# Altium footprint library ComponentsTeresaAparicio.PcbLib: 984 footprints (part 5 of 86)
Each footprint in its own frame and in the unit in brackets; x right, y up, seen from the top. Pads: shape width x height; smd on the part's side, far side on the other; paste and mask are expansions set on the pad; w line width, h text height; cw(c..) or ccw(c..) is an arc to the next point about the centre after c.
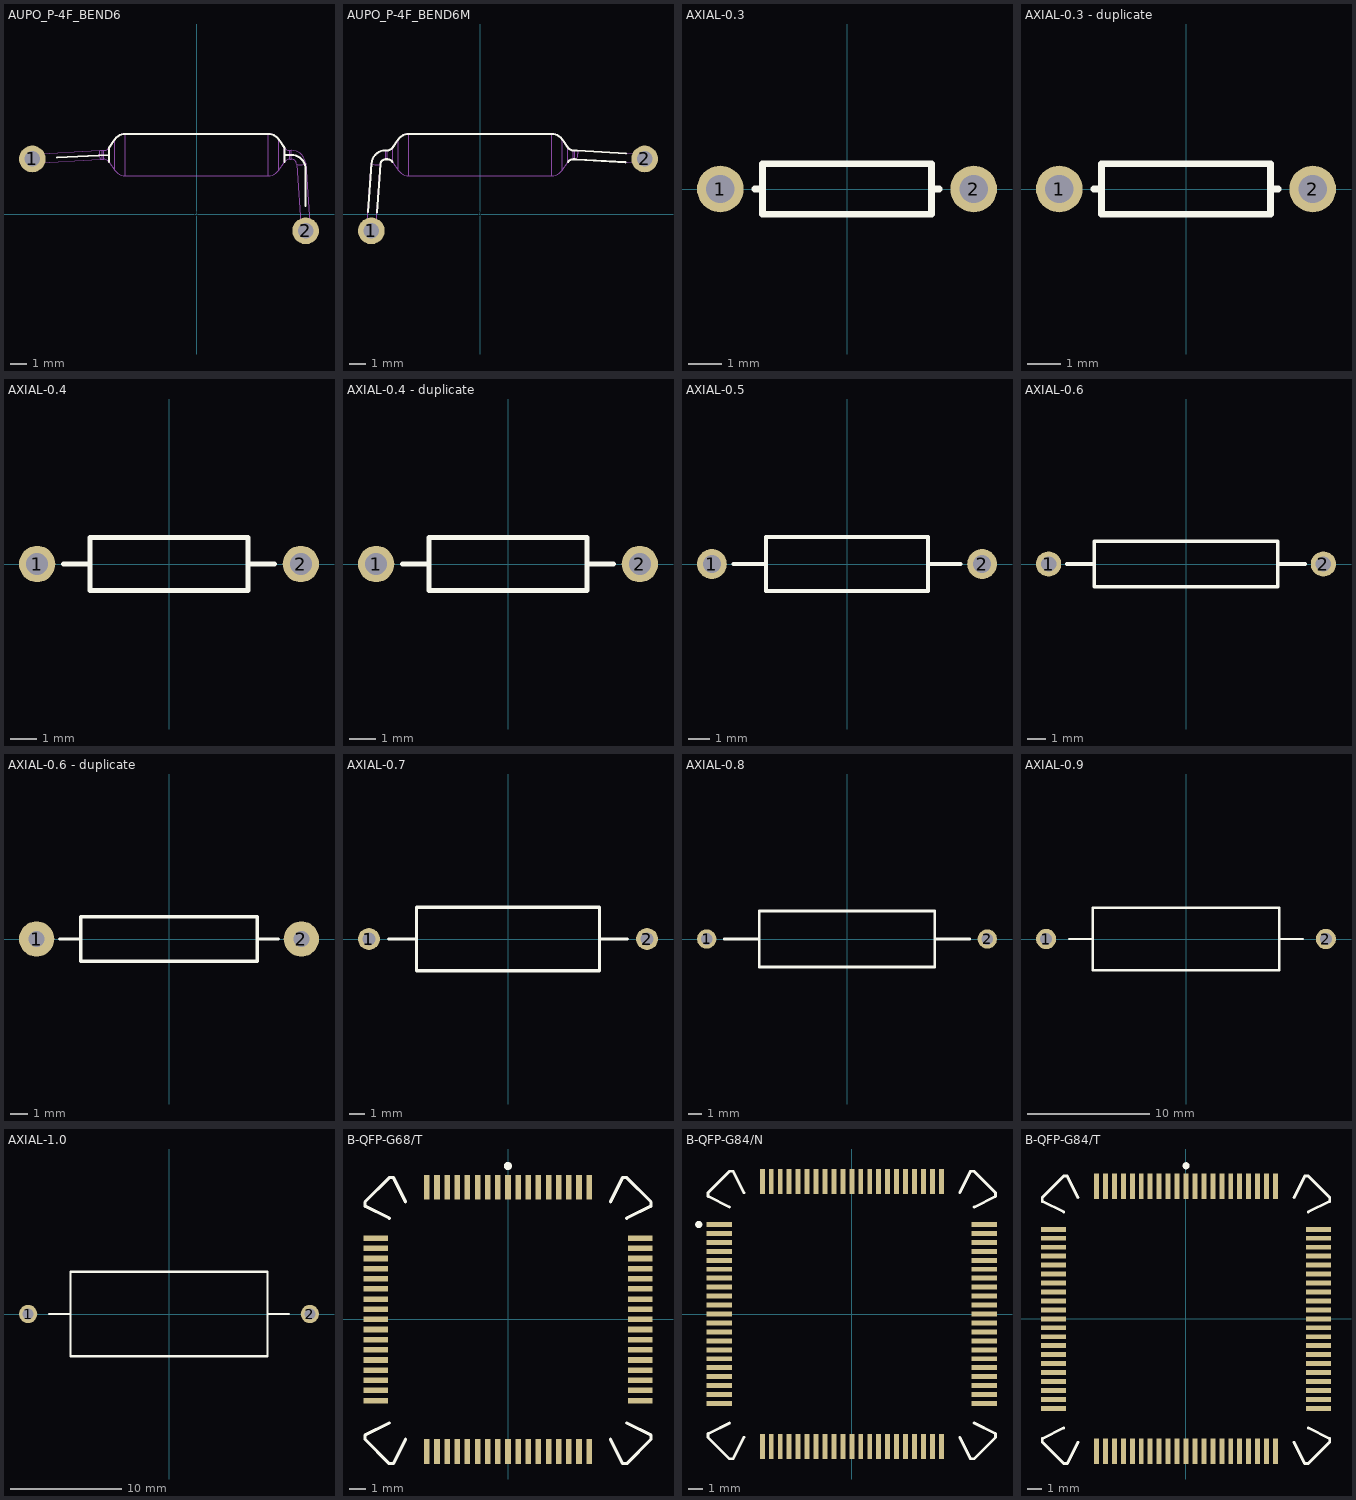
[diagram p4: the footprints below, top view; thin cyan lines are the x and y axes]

## AUPO_P-4F_BEND6 [mil] "Aupo P-4F TCO for positioning on IC legs"
height 100
pads (3):
  round 19.68 on Mech14: 0(0,0)
  round 65 / inner round 65 / far side round 90 hole 38: 1(-400,135) 2(265,-40)
Top Overlay:
  lines w5: -340.17,138.21 -213.48,145 ; -213.48,127.46 -213.48,162.54 -199.33,182.75 cw(c-173.53,164.69) -173.53,196.18 173.53,196.18 cw(c173.53,164.69) 199.33,182.75 213.48,162.54 213.48,127.46 ; 213.48,145 230,145 cw(c230,110) 265,110 265,20
Mechanical 13:
  lines w1.97: -381.43,146.96 ccw(c-359.97,137.39) -380.14,125.34 ; 252.86,-21.08 ccw(c262.11,4.31) 274.45,-19.73 274.46,-19.61 ; -235.55,155.67 ccw(c-214.1,146.11) -234.26,134.06 ; -235.55,155.67 -400.65,145.81 ccw(c-400,135) -399.35,124.19 -234.26,134.06 ; -235.55,155.67 -232.3,155.8 -230.32,155.83 ; -234.26,134.06 -232.78,134.13 -230.32,134.17 ; -230.32,134.17 -230.32,155.83 ; -230.32,134.17 -226.38,134.17 ; -230.32,155.83 -226.38,155.83 ; -226.38,134.17 cw(c-226.38,118.43) -213.48,127.46 ; -226.38,134.17 -226.38,155.83 ; -226.38,155.83 ccw(c-226.38,171.57) -213.48,162.54 ; -213.48,127.46 -199.33,107.25 ; -213.48,127.46 -213.48,162.54 ; -213.48,162.54 -199.33,182.75 ; -199.33,107.25 ccw(c-173.53,125.31) -173.53,93.82 ; -199.33,107.25 -199.33,182.75 ; -199.33,182.75 cw(c-173.53,164.69) -173.53,196.18 ; -173.53,93.82 -173.53,196.18 ; -173.53,93.82 173.53,93.82 ; -173.53,196.18 173.53,196.18 ; 173.53,93.82 ccw(c173.53,125.31) 199.33,107.25 ; 173.53,93.82 173.53,196.18 ; 173.53,196.18 cw(c173.53,164.69) 199.33,182.75 ; 199.33,107.25 199.33,182.75 ; 199.33,107.25 213.48,127.46 ; 199.33,182.75 213.48,162.54 ; 213.48,127.46 cw(c226.38,118.43) 226.38,134.17 ; 213.48,127.46 213.48,162.54 ; 213.48,162.54 ccw(c226.38,171.57) 226.38,155.83 ; 226.38,134.17 226.38,155.83 ; 226.38,134.17 230.32,134.17 ; 226.38,155.83 230.32,155.83 ; 230.32,134.17 cw(c230.47,121.52) 243.08,122.53 ; 230.32,134.17 230.32,155.83 ; 230.32,155.83 cw(c230.46,121.51) 264.69,124 ; 243.08,122.53 ccw(c252.33,147.93) 264.67,123.88 264.69,124 ; 243.08,122.53 254.2,-40.74 ccw(c265,-40) 275.83,-40 275.8,-39.26 264.69,124
3D body: height 40, standoff 0, extent -445,90.09 -355.36,179.91
3D body: height 102.87, standoff -99.49, extent -410.74,-50.8 275.83,196.09
3D body: height 40, standoff 0, extent 219.99,-84.91 309.64,4.91

## AUPO_P-4F_BEND6M [mil] "Aupo P-4F TCO for positioning on IC legs"
height 100
pads (3):
  round 19.68 on Mech14: 0(0,0)
  round 65 / inner round 65 / far side round 90 hole 38: 1(-265,-40) 2(400,135)
Top Overlay:
  lines w5: -272.66,6.54 -264.69,124.01 cw(c-230.48,121.53) -230.32,155.83 -226.38,155.83 ccw(c-226.38,171.57) -213.48,162.54 -199.33,182.75 cw(c-173.53,164.69) -173.53,196.18 173.53,196.18 cw(c173.53,164.69) 199.33,182.75 213.48,162.54 ccw(c226.38,171.57) 226.38,155.83 230.32,155.83 233.67,155.76 235.64,155.67 354.91,148.54 ; -251.05,5.07 -243.08,122.54 cw(c-230.46,121.51) -230.32,134.17 -226.38,134.17 cw(c-226.38,118.43) -213.48,127.46 ; 213.48,127.46 cw(c226.38,118.43) 226.38,134.17 230.32,134.17 231.82,134.16 234.34,134.05 353.62,126.93
Mechanical 13:
  lines w1.97: -274.43,-19.69 ccw(c-262.06,2.73) -252.83,-21.16 ; 380.23,125.34 ccw(c367.39,134.41) 382.95,136.67 383.02,139.06 382.98,141.3 382.83,143.28 382.58,144.91 382.25,146.1 381.85,146.78 381.52,146.95 ; -264.69,124.01 ccw(c-252.3,146.47) -243.08,122.54 ; -264.69,124.01 cw(c-230.48,121.53) -230.32,155.83 ; -264.69,124.01 -275.76,-39.27 ccw(c-264.96,-40) -254.16,-40.73 -243.08,122.54 ; -243.08,122.54 cw(c-230.46,121.51) -230.32,134.17 ; -230.32,134.17 -230.32,155.83 ; -230.32,134.17 -226.38,134.17 ; -230.32,155.83 -226.38,155.83 ; -226.38,134.17 cw(c-226.38,118.43) -213.48,127.46 ; -226.38,134.17 -226.38,155.83 ; -226.38,155.83 ccw(c-226.38,171.57) -213.48,162.54 ; -213.48,127.46 -213.48,162.54 ; -213.48,127.46 -199.33,107.25 ; -213.48,162.54 -199.33,182.75 ; -199.33,107.25 ccw(c-173.53,125.31) -173.53,93.82 ; -199.33,107.25 -199.33,182.75 ; -199.33,182.75 cw(c-173.53,164.69) -173.53,196.18 ; -173.53,93.82 -173.53,196.18 ; -173.53,93.82 173.53,93.82 ; -173.53,196.18 173.53,196.18 ; 173.53,93.82 ccw(c173.53,125.31) 199.33,107.25 ; 173.53,93.82 173.53,196.18 ; 173.53,196.18 cw(c173.53,164.69) 199.33,182.75 ; 199.33,107.25 199.33,182.75 ; 199.33,107.25 213.48,127.46 ; 199.33,182.75 213.48,162.54 ; 213.48,127.46 cw(c226.38,118.43) 226.38,134.17 ; 213.48,127.46 213.48,162.54 ; 213.48,162.54 ccw(c226.38,171.57) 226.38,155.83 ; 226.38,134.17 226.38,155.83 ; 226.38,134.17 230.32,134.17 ; 226.38,155.83 230.32,155.83 ; 230.32,134.17 230.32,155.83 ; 230.32,134.17 231.82,134.16 234.34,134.05 ; 230.32,155.83 233.67,155.76 235.64,155.67 ; 234.34,134.05 ccw(c221.51,143.13) 237.07,145.38 237.13,147.77 237.09,150.02 236.94,152 236.69,153.63 236.36,154.82 235.96,155.5 235.64,155.67 ; 234.34,134.05 399.35,124.19 ccw(c400,135) 400.65,145.81 235.64,155.67
3D body: height 40, standoff 0, extent -309.64,-84.91 -220,4.92
3D body: height 102.95, standoff -100, extent -275.7,-50.8 410.83,196.09
3D body: height 40, standoff 0, extent 355.36,90.1 445,179.92

## AXIAL-0.3 [mm] "Axial Device, Thru-Hole; 2 Leads; 0.3 in Pin Spacing"
height 1.524
pads (2):
  round 1.4 hole 0.85: 1(-3.81,0) 2(3.81,0)
Top Overlay:
  lines w0.2: -2.769,0 -2.54,0 ; 2.769,0 2.54,0 ; 2.54,0 2.54,0.762 -2.54,0.762 -2.54,-0.762 2.54,-0.762 2.54,0

## AXIAL-0.3 - duplicate [mm] "Axial Device, Thru-Hole; 2 Leads; 0.3 in Pin Spacing"
height 1.524
pads (2):
  round 1.4 hole 0.85: 1(-3.81,0) 2(3.81,0)
Top Overlay:
  lines w0.2: -2.769,0 -2.54,0 ; 2.769,0 2.54,0 ; 2.54,0 2.54,0.762 -2.54,0.762 -2.54,-0.762 2.54,-0.762 2.54,0

## AXIAL-0.4 [mm] "Axial Device, Thru-Hole; 2 Leads; 0.4 in Pin Spacing"
height 2.032
pads (2):
  round 1.4 hole 0.85: 1(-5.08,0) 2(5.08,0)
Top Overlay:
  lines w0.2: -4.064,0 -3.048,0 ; 3.048,0 4.064,0 ; -3.048,-1.016 -3.048,1.016 3.048,1.016 3.048,-1.016 -3.048,-1.016

## AXIAL-0.4 - duplicate [mm] "Axial Device, Thru-Hole; 2 Leads; 0.4 in Pin Spacing"
height 2.032
pads (2):
  round 1.4 hole 0.85: 1(-5.08,0) 2(5.08,0)
Top Overlay:
  lines w0.2: -4.064,0 -3.048,0 ; 3.048,0 4.064,0 ; -3.048,-1.016 3.048,-1.016 3.048,1.016 -3.048,1.016 -3.048,-1.016
3D body: height 3.2, standoff -1.25, extent -5.15,-1.13 5.15,1.27

## AXIAL-0.5 [mm] "Axial Device, Thru-Hole; 2 Leads; 0.5 in Pin Spacing"
height 2.54
pads (2):
  round 1.4 hole 0.85: 1(-6.35,0) 2(6.35,0)
Top Overlay:
  lines w0.2: -5.334,0 -3.81,0 ; 3.81,0 5.334,0 ; -3.81,-1.27 -3.81,1.27 3.81,1.27 3.81,-1.27 -3.81,-1.27

## AXIAL-0.6 [mm] "Axial Device, Thru-Hole; 2 Leads; 0.6 in Pin Spacing"
height 2.54
pads (2):
  round 1.4 hole 0.85: 1(-7.62,0) 2(7.62,0)
Top Overlay:
  lines w0.2: -6.604,0 -5.08,0 ; 5.08,0 6.604,0 ; -5.08,-1.27 5.08,-1.27 5.08,1.27 -5.08,1.27 -5.08,-1.27

## AXIAL-0.6 - duplicate [mil] "Axial Device, Thru-Hole; 2 Leads; 0.6 in Pin Spacing"
height 100
pads (2):
  round 80 hole 36: 1(-300,0) 2(300,0)
Top Overlay:
  lines w7.87: -248.03,0 -200,0 ; 200,0 248.03,0 ; -200,-50 -200,50 200,50 200,-50 -200,-50
3D body: height 102.76, standoff -98.43, extent -311.8,-51.57 311.82,51.58

## AXIAL-0.7 [mm] "Axial Device, Thru-Hole; 2 Leads; 0.7 in Pin Spacing"
height 4.064
pads (2):
  round 1.4 hole 0.85: 1(-8.89,0) 2(8.89,0)
Top Overlay:
  lines w0.2: -7.62,0 -5.842,0 ; 5.842,0 7.62,0 ; -5.842,-2.032 5.842,-2.032 5.842,2.032 -5.842,2.032 -5.842,-2.032

## AXIAL-0.8 [mm] "Axial Device, Thru-Hole; 2 Leads; 0.8 in Pin Spacing"
height 4.064
pads (2):
  round 1.4 hole 0.85: 1(-10.16,0) 2(10.16,0)
Top Overlay:
  lines w0.2: -8.89,0 -6.35,0 ; 6.35,0 8.89,0 ; -6.35,-2.032 -6.35,2.032 6.35,2.032 6.35,-2.032 -6.35,-2.032

## AXIAL-0.9 [mm] "Axial Device, Thru-Hole; 2 Leads; 0.9 in Pin Spacing"
height 5.08
pads (2):
  round 1.65 hole 1: 1(-11.43,0) 2(11.43,0)
Top Overlay:
  lines w0.2: -9.525,0 -7.62,0 ; 7.62,0 9.525,0 ; -7.62,-2.54 7.62,-2.54 7.62,2.54 -7.62,2.54 -7.62,-2.54

## AXIAL-1.0 [mm] "Axial Device, Thru-Hole; 2 Leads; 1.0 in Pin Spacing"
height 7.62
pads (2):
  round 1.65 hole 1: 1(-12.7,0) 2(12.7,0)
Top Overlay:
  lines w0.2: -10.795,0 -8.89,0 ; 8.89,0 10.795,0 ; -8.89,-3.81 -8.89,3.81 8.89,3.81 8.89,-3.81 -8.89,-3.81

## B-QFP-G68/T [mm] "PQFP; 68 Leads; Body 14 x 14 mm; Pitch 0.635 mm"
height 3.04
pads (68):
  rect 0.35x1.55 smd: 1(0,8.275) 2(-0.635,8.275) 3(-1.27,8.275) 4(-1.905,8.275) 5(-2.54,8.275) 6(-3.175,8.275) 7(-3.81,8.275) 8(-4.445,8.275) 9(-5.08,8.275) 27(-5.08,-8.275) 28(-4.445,-8.275) 29(-3.81,-8.275) 30(-3.175,-8.275) 31(-2.54,-8.275) 32(-1.905,-8.275) 33(-1.27,-8.275) 34(-0.635,-8.275) 35(0,-8.275) 36(0.635,-8.275) 37(1.27,-8.275) 38(1.905,-8.275) 39(2.54,-8.275) 40(3.175,-8.275) 41(3.81,-8.275) 42(4.445,-8.275) 43(5.08,-8.275) 61(5.08,8.275) 62(4.445,8.275) 63(3.81,8.275) 64(3.175,8.275) 65(2.54,8.275) 66(1.905,8.275) 67(1.27,8.275) 68(0.635,8.275)
  rect 1.55x0.35 smd: 10(-8.275,5.08) 11(-8.275,4.445) 12(-8.275,3.81) 13(-8.275,3.175) 14(-8.275,2.54) 15(-8.275,1.905) 16(-8.275,1.27) 17(-8.275,0.635) 18(-8.275,0) 19(-8.275,-0.635) 20(-8.275,-1.27) 21(-8.275,-1.905) 22(-8.275,-2.54) 23(-8.275,-3.175) 24(-8.275,-3.81) 25(-8.275,-4.445) 26(-8.275,-5.08) 44(8.275,-5.08) 45(8.275,-4.445) 46(8.275,-3.81) 47(8.275,-3.175) 48(8.275,-2.54) 49(8.275,-1.905) 50(8.275,-1.27) 51(8.275,-0.635) 52(8.275,0) 53(8.275,0.635) 54(8.275,1.27) 55(8.275,1.905) 56(8.275,2.54) 57(8.275,3.175) 58(8.275,3.81) 59(8.275,4.445) 60(8.275,5.08)
Top Overlay:
  circle w0.25: c0,9.6 r0.125
  lines w0.2: -8.95,-7.247 -7.426,-6.485 ; -8.95,-7.229 -8.95,-7.501 -7.426,-9.025 -7.172,-9.025 -6.41,-7.501 ; -8.95,7.079 -8.95,7.351 -7.426,8.875 -7.172,8.875 -6.41,7.351 ; -8.95,7.097 -7.426,6.335 ; 6.41,-7.501 7.172,-9.025 7.426,-9.025 8.95,-7.501 8.95,-7.229 ; 6.41,7.351 7.172,8.875 7.426,8.875 8.95,7.351 8.95,7.079 ; 7.426,-6.485 8.95,-7.247 ; 7.426,6.335 8.95,7.097

## B-QFP-G84/N [mm] "PQFP; 84 Leads; Body 16.5 x 16.5 mm; Pitch 0.635 mm"
height 4.57
pads (84):
  rect 1.8x0.35 smd: 1(-9.4,6.35) 2(-9.4,5.715) 3(-9.4,5.08) 4(-9.4,4.445) 5(-9.4,3.81) 6(-9.4,3.175) 7(-9.4,2.54) 8(-9.4,1.905) 9(-9.4,1.27) 10(-9.4,0.635) 11(-9.4,0) 12(-9.4,-0.635) 13(-9.4,-1.27) 14(-9.4,-1.905) 15(-9.4,-2.54) 16(-9.4,-3.175) 17(-9.4,-3.81) 18(-9.4,-4.445) 19(-9.4,-5.08) 20(-9.4,-5.715) 21(-9.4,-6.35) 43(9.4,-6.35) 44(9.4,-5.715) 45(9.4,-5.08) 46(9.4,-4.445) 47(9.4,-3.81) 48(9.4,-3.175) 49(9.4,-2.54) 50(9.4,-1.905) 51(9.4,-1.27) 52(9.4,-0.635) 53(9.4,0) 54(9.4,0.635) 55(9.4,1.27) 56(9.4,1.905) 57(9.4,2.54) 58(9.4,3.175) 59(9.4,3.81) 60(9.4,4.445) 61(9.4,5.08) 62(9.4,5.715) 63(9.4,6.35)
  rect 0.35x1.8 smd: 22(-6.35,-9.4) 23(-5.715,-9.4) 24(-5.08,-9.4) 25(-4.445,-9.4) 26(-3.81,-9.4) 27(-3.175,-9.4) 28(-2.54,-9.4) 29(-1.905,-9.4) 30(-1.27,-9.4) 31(-0.635,-9.4) 32(0,-9.4) 33(0.635,-9.4) 34(1.27,-9.4) 35(1.905,-9.4) 36(2.54,-9.4) 37(3.175,-9.4) 38(3.81,-9.4) 39(4.445,-9.4) 40(5.08,-9.4) 41(5.715,-9.4) 42(6.35,-9.4) 64(6.35,9.4) 65(5.715,9.4) 66(5.08,9.4) 67(4.445,9.4) 68(3.81,9.4) 69(3.175,9.4) 70(2.54,9.4) 71(1.905,9.4) 72(1.27,9.4) 73(0.635,9.4) 74(0,9.4) 75(-0.635,9.4) 76(-1.27,9.4) 77(-1.905,9.4) 78(-2.54,9.4) 79(-3.175,9.4) 80(-3.81,9.4) 81(-4.445,9.4) 82(-5.08,9.4) 83(-5.715,9.4) 84(-6.35,9.4)
Top Overlay:
  circle w0.25: c-10.86,6.35 r0.125
  lines w0.2: -10.2,-8.497 -8.676,-7.735 ; -10.2,-8.479 -10.2,-8.751 -8.676,-10.275 -8.422,-10.275 -7.66,-8.751 ; -10.2,8.329 -10.2,8.601 -8.676,10.125 -8.422,10.125 -7.66,8.601 ; -10.2,8.347 -8.676,7.585 ; 7.66,-8.751 8.422,-10.275 8.676,-10.275 10.2,-8.751 10.2,-8.479 ; 7.66,8.601 8.422,10.125 8.676,10.125 10.2,8.601 10.2,8.329 ; 8.676,-7.735 10.2,-8.497 ; 8.676,7.585 10.2,8.347

## B-QFP-G84/T [mm] "PQFP; 84 Leads; Body 16.5 x 16.5 mm; Pitch 0.635 mm"
height 4.57
pads (84):
  rect 0.35x1.8 smd: 1(0,9.4) 2(-0.635,9.4) 3(-1.27,9.4) 4(-1.905,9.4) 5(-2.54,9.4) 6(-3.175,9.4) 7(-3.81,9.4) 8(-4.445,9.4) 9(-5.08,9.4) 10(-5.715,9.4) 11(-6.35,9.4) 33(-6.35,-9.4) 34(-5.715,-9.4) 35(-5.08,-9.4) 36(-4.445,-9.4) 37(-3.81,-9.4) 38(-3.175,-9.4) 39(-2.54,-9.4) 40(-1.905,-9.4) 41(-1.27,-9.4) 42(-0.635,-9.4) 43(0,-9.4) 44(0.635,-9.4) 45(1.27,-9.4) 46(1.905,-9.4) 47(2.54,-9.4) 48(3.175,-9.4) 49(3.81,-9.4) 50(4.445,-9.4) 51(5.08,-9.4) 52(5.715,-9.4) 53(6.35,-9.4) 75(6.35,9.4) 76(5.715,9.4) 77(5.08,9.4) 78(4.445,9.4) 79(3.81,9.4) 80(3.175,9.4) 81(2.54,9.4) 82(1.905,9.4) 83(1.27,9.4) 84(0.635,9.4)
  rect 1.8x0.35 smd: 12(-9.4,6.35) 13(-9.4,5.715) 14(-9.4,5.08) 15(-9.4,4.445) 16(-9.4,3.81) 17(-9.4,3.175) 18(-9.4,2.54) 19(-9.4,1.905) 20(-9.4,1.27) 21(-9.4,0.635) 22(-9.4,0) 23(-9.4,-0.635) 24(-9.4,-1.27) 25(-9.4,-1.905) 26(-9.4,-2.54) 27(-9.4,-3.175) 28(-9.4,-3.81) 29(-9.4,-4.445) 30(-9.4,-5.08) 31(-9.4,-5.715) 32(-9.4,-6.35) 54(9.4,-6.35) 55(9.4,-5.715) 56(9.4,-5.08) 57(9.4,-4.445) 58(9.4,-3.81) 59(9.4,-3.175) 60(9.4,-2.54) 61(9.4,-1.905) 62(9.4,-1.27) 63(9.4,-0.635) 64(9.4,0) 65(9.4,0.635) 66(9.4,1.27) 67(9.4,1.905) 68(9.4,2.54) 69(9.4,3.175) 70(9.4,3.81) 71(9.4,4.445) 72(9.4,5.08) 73(9.4,5.715) 74(9.4,6.35)
Top Overlay:
  circle w0.25: c0,10.86 r0.125
  lines w0.2: -10.2,-8.497 -8.676,-7.735 ; -10.2,-8.479 -10.2,-8.751 -8.676,-10.275 -8.422,-10.275 -7.66,-8.751 ; -10.2,8.329 -10.2,8.601 -8.676,10.125 -8.422,10.125 -7.66,8.601 ; -10.2,8.347 -8.676,7.585 ; 7.66,-8.751 8.422,-10.275 8.676,-10.275 10.2,-8.751 10.2,-8.479 ; 7.66,8.601 8.422,10.125 8.676,10.125 10.2,8.601 10.2,8.329 ; 8.676,-7.735 10.2,-8.497 ; 8.676,7.585 10.2,8.347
